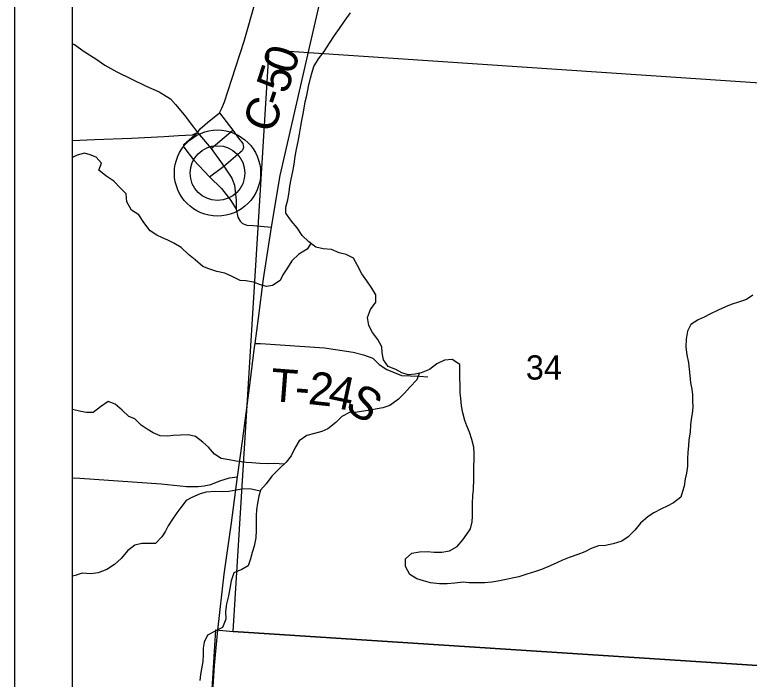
# Model space of a CAD drawing. Extents: x 0 to 34, y 0 to 22.
# Drawn here: x 23.417 to 24.685, y 19.088 to 20.236 of the extents above; entities that cross this region are included whole.
import ezdxf

# ---------------------------------------------------------------- set-up
doc = ezdxf.new("R2010")
doc.units = 0
for name, color, linetype in [('GM_X_County_Road', 7, 'Continuous'), ('GM_X_County_Road_Text', 7, 'Continuous'), ('GM_X_Minor_River', 7, 'Continuous'), ('GM_X_Section', 7, 'Continuous'), ('GM_X_Section_Text', 7, 'Continuous'), ('GM_X_State_Route', 7, 'Continuous'), ('GM_X_Township_Road', 7, 'Continuous'), ('GM_X_Township_Road_Text', 7, 'Continuous'), ('GM_X_Unincorporated', 7, 'Continuous'), ('GM_X_Unincorporated_Location', 7, 'Continuous'), ('SH_Data', 7, 'Continuous')]:
    doc.layers.add(name, color=color, linetype=linetype)

msp = doc.modelspace()

# ---------------------------------------------------------------- linework, layer by layer
at = {"layer": 'GM_X_County_Road'}
for points in [[(23.7323, 20.033), (23.737, 20.0391), (23.7498, 20.0501), (23.7703, 20.0665), (23.7745, 20.0748), (23.779, 20.0858), (23.7916, 20.1246), (23.8127, 20.1904), (23.833, 20.2612), (23.8405, 20.2846), (23.8637, 20.3631), (23.8706, 20.3822), (23.8749, 20.3912)], [(23.5167, 20.019), (23.5544, 20.0206), (23.6182, 20.0227), (23.675, 20.0261), (23.6994, 20.0275), (23.7237, 20.0287), (23.7323, 20.033), (23.7558, 20.005), (23.7778, 19.9748), (23.7918, 19.9541), (23.7964, 19.9419), (23.799, 19.9157), (23.799, 19.9003), (23.8022, 19.8863), (23.8061, 19.8796), (23.8102, 19.8755), (23.8176, 19.8729), (23.8286, 19.872), (23.8599, 19.8692)]]:
    msp.add_lwpolyline(points, dxfattribs=at)
at = {"layer": 'GM_X_Minor_River'}
for points in [[(24.1853, 19.6088), (24.1856, 19.6217), (24.1852, 19.632), (24.1719, 19.6407), (24.1591, 19.6395), (24.1455, 19.633), (24.133, 19.6235), (24.1186, 19.6178), (24.1081, 19.6151), (24.0959, 19.6143), (24.0853, 19.6177), (24.0751, 19.6234), (24.0618, 19.6286), (24.0535, 19.64), (24.0515, 19.6529), (24.0507, 19.6623), (24.0435, 19.6752), (24.0348, 19.6873), (24.0283, 19.6994), (24.026, 19.7131), (24.0312, 19.7271), (24.0403, 19.74), (24.0402, 19.7522), (24.0334, 19.7639), (24.025, 19.7764), (24.0159, 19.7889), (24.0086, 19.8029), (24.0018, 19.8158), (23.9889, 19.8222), (23.9768, 19.8252), (23.9635, 19.8308), (23.9491, 19.8316), (23.9366, 19.8346), (23.9245, 19.844), (23.9131, 19.855), (23.9043, 19.8682), (23.8948, 19.8799), (23.885, 19.8936), (23.8849, 19.9038), (23.8883, 19.9163), (23.8905, 19.9296), (23.892, 19.9402), (23.8942, 19.9523), (23.8968, 19.9656), (23.8991, 19.9778), (23.9009, 19.9914), (23.9031, 20.0039), (23.9061, 20.0172), (23.9087, 20.0297), (23.911, 20.0434), (23.9128, 20.0536), (23.9151, 20.065), (23.9165, 20.0748), (23.9184, 20.0858), (23.921, 20.0968), (23.924, 20.1124), (23.9274, 20.1264), (23.9304, 20.1367), (23.9333, 20.1465), (23.9413, 20.1602), (23.9511, 20.1727), (23.9605, 20.1868), (23.9691, 20.2001), (23.9778, 20.2122), (23.9861, 20.2251), (23.9963, 20.2392)], [(23.9282, 19.8411), (23.9215, 19.8311), (23.9075, 19.8224), (23.8954, 19.811), (23.8879, 19.7992), (23.88, 19.7867), (23.8751, 19.7772), (23.8619, 19.7684), (23.8513, 19.7669), (23.8414, 19.7695), (23.8293, 19.774), (23.8161, 19.7766), (23.8058, 19.777), (23.7922, 19.7842), (23.7793, 19.7898), (23.7657, 19.7924), (23.752, 19.7973), (23.7418, 19.8015), (23.7285, 19.8128), (23.7171, 19.8223), (23.7042, 19.834), (23.6913, 19.8419), (23.6814, 19.8468), (23.672, 19.851), (23.6621, 19.8555), (23.6504, 19.863), (23.6397, 19.8774), (23.6313, 19.8907), (23.6184, 19.8986), (23.6104, 19.913), (23.6093, 19.9266), (23.5994, 19.9368), (23.5876, 19.9489), (23.5743, 19.958), (23.5622, 19.9678), (23.5663, 19.9796), (23.5572, 19.9902), (23.547, 19.9943), (23.5375, 19.997), (23.5246, 19.9935), (23.5167, 19.9895)], [(24.6913, 19.7519), (24.6804, 19.7446), (24.6683, 19.7404), (24.6539, 19.7355), (24.6441, 19.7317), (24.6316, 19.7259), (24.6172, 19.7191)], [(24.6172, 19.7191), (24.6074, 19.7138), (24.5972, 19.7092), (24.584, 19.7012), (24.5783, 19.6894), (24.5761, 19.6761), (24.5754, 19.6621), (24.5773, 19.6489), (24.5804, 19.6352), (24.5812, 19.6238), (24.5824, 19.6132), (24.5839, 19.6003), (24.5859, 19.5897), (24.587, 19.5795), (24.5874, 19.5696), (24.5875, 19.5583), (24.5864, 19.5473), (24.5849, 19.5374), (24.5838, 19.5276), (24.5831, 19.515), (24.5808, 19.5021), (24.5805, 19.4923), (24.579, 19.4798), (24.5783, 19.4695), (24.5783, 19.4566), (24.5769, 19.4445), (24.5746, 19.4347), (24.5728, 19.4221), (24.5701, 19.4127), (24.5672, 19.4032), (24.5543, 19.3929), (24.5434, 19.3876), (24.5335, 19.383), (24.5203, 19.3758), (24.5105, 19.3697), (24.4976, 19.3579), (24.4875, 19.3461), (24.4761, 19.3343), (24.4652, 19.3267), (24.4501, 19.3221), (24.4372, 19.3194), (24.4247, 19.3187), (24.4119, 19.3141), (24.4013, 19.3087), (24.3892, 19.3038), (24.3741, 19.2988), (24.3627, 19.2939), (24.3529, 19.2897), (24.3415, 19.2843), (24.3264, 19.2782), (24.3158, 19.2744), (24.3011, 19.2698), (24.2871, 19.2656), (24.2757, 19.2633), (24.2655, 19.261), (24.2512, 19.2576), (24.2406, 19.2564), (24.2285, 19.2552), (24.2156, 19.2548), (24.2016, 19.2552), (24.1914, 19.2559), (24.177, 19.2544), (24.1634, 19.2532), (24.1505, 19.2532), (24.135, 19.255), (24.1228, 19.2584), (24.1111, 19.2618), (24.0993, 19.2693), (24.0913, 19.283), (24.0913, 19.2962), (24.1022, 19.3061), (24.1155, 19.3084), (24.1287, 19.3092), (24.1408, 19.3081), (24.1541, 19.3078), (24.1677, 19.3104), (24.1806, 19.3177), (24.1907, 19.3291), (24.1975, 19.339), (24.2039, 19.3484), (24.2069, 19.3602), (24.2073, 19.3701), (24.2072, 19.3921), (24.2079, 19.4061), (24.209, 19.4156), (24.2093, 19.4345), (24.2093, 19.4463), (24.2096, 19.4561), (24.2104, 19.4679), (24.2103, 19.4781), (24.2095, 19.4891), (24.2061, 19.5024), (24.2023, 19.5153), (24.1977, 19.5259), (24.1942, 19.5353), (24.1904, 19.5486), (24.1881, 19.5607), (24.1869, 19.5732), (24.1858, 19.5834), (24.1857, 19.5956), (24.1853, 19.6088)], [(24.1149, 19.6168), (24.1111, 19.6053), (24.099, 19.5931), (24.0896, 19.5825), (24.0794, 19.5722), (24.0647, 19.5615), (24.0526, 19.5573), (24.0428, 19.5554), (24.0303, 19.5531), (24.0197, 19.5512), (24.0083, 19.55), (23.9951, 19.5489), (23.9815, 19.542), (23.9713, 19.5317), (23.9577, 19.5207), (23.9471, 19.5161), (23.9343, 19.5131), (23.9214, 19.5093), (23.9082, 19.5005), (23.9006, 19.4876), (23.8943, 19.4743), (23.8856, 19.4633), (23.8739, 19.4527), (23.8607, 19.439), (23.8509, 19.4261), (23.8411, 19.415), (23.8381, 19.4048), (23.8358, 19.3927), (23.834, 19.3813), (23.8336, 19.3707), (23.8337, 19.3559), (23.8337, 19.3457), (23.833, 19.3328), (23.83, 19.3183), (23.827, 19.3073), (23.8237, 19.2967), (23.8199, 19.2842), (23.809, 19.2781), (23.7953, 19.2724), (23.7905, 19.2584), (23.7882, 19.2451), (23.786, 19.2326), (23.7826, 19.2189), (23.7808, 19.2056), (23.7812, 19.192), (23.7756, 19.1776), (23.7627, 19.1715), (23.7495, 19.1646), (23.7439, 19.1525), (23.7424, 19.1422), (23.7424, 19.1309), (23.7417, 19.1191), (23.7395, 19.1066), (23.7376, 19.0967), (23.7361, 19.0861)], [(23.8817, 19.4597), (23.8655, 19.461), (23.8538, 19.4606), (23.8398, 19.4609), (23.8262, 19.462), (23.8163, 19.4628), (23.7993, 19.4654), (23.7871, 19.4672), (23.7735, 19.4695), (23.7618, 19.477), (23.7511, 19.4891), (23.7416, 19.4982), (23.7287, 19.5077), (23.7162, 19.5107), (23.703, 19.5099), (23.6905, 19.5095), (23.6806, 19.5083), (23.6678, 19.5086), (23.656, 19.5143), (23.6454, 19.5203), (23.6352, 19.5271), (23.6241, 19.5381), (23.6135, 19.5422), (23.6021, 19.5532), (23.5904, 19.5638), (23.5782, 19.5679), (23.5646, 19.5592), (23.5522, 19.5493), (23.5405, 19.5489), (23.5306, 19.5508), (23.5167, 19.5544)], [(23.8406, 19.4135), (23.8225, 19.4173), (23.8093, 19.4169), (23.7994, 19.4153), (23.7866, 19.4126), (23.7756, 19.4119), (23.7627, 19.4126), (23.7476, 19.4118), (23.737, 19.4087), (23.7226, 19.4022), (23.7128, 19.3973), (23.7038, 19.3851), (23.6966, 19.3756), (23.6879, 19.3635), (23.6819, 19.3536), (23.677, 19.3441), (23.671, 19.3346), (23.6597, 19.3229), (23.6362, 19.3228), (23.6241, 19.3201), (23.6116, 19.3102), (23.6003, 19.2973), (23.589, 19.2867), (23.5758, 19.2783), (23.561, 19.2722), (23.5482, 19.2707), (23.5334, 19.2718), (23.5213, 19.2679), (23.5167, 19.2666)]]:
    msp.add_lwpolyline(points, dxfattribs=at)
at = {"layer": 'GM_X_Section'}
for points in [[(24.8672, 20.1076), (24.8107, 19.1055), (24.788, 19.1066), (23.7939, 19.171), (23.856, 20.1758)], [(23.7643, 19.174), (23.7939, 19.171), (24.788, 19.1066), (24.7175, 18.0761), (23.7006, 18.1492)]]:
    msp.add_lwpolyline(points, close=True, dxfattribs=at)
at = {"layer": 'GM_X_State_Route'}
for points in [[(23.8012, 19.4381), (23.8098, 19.4995), (23.8164, 19.5483), (23.8228, 19.5962), (23.8308, 19.6618), (23.8317, 19.6681), (23.8378, 19.712), (23.8466, 19.7798), (23.8599, 19.8692), (23.875, 19.9586), (23.9292, 20.1943), (23.96, 20.3273), (23.9665, 20.3566)], [(23.7042, 18.1483), (23.71, 18.2567), (23.7163, 18.3616), (23.7166, 18.3673), (23.7229, 18.4696), (23.7282, 18.5549), (23.7307, 18.6019), (23.7382, 18.7246), (23.7401, 18.752), (23.743, 18.7962), (23.7497, 18.9118), (23.7506, 18.9339), (23.7569, 19.0384), (23.7617, 19.1125), (23.7675, 19.1733), (23.7785, 19.2701), (23.7909, 19.3586), (23.8012, 19.4381)]]:
    msp.add_lwpolyline(points, dxfattribs=at)
at = {"layer": 'GM_X_Township_Road'}
msp.add_line((23.7558, 20.005), (23.7936, 20.0369), dxfattribs=at)
for points in [[(23.5167, 20.1861), (23.5199, 20.1845), (23.5366, 20.1727), (23.5569, 20.1597), (23.5725, 20.1491), (23.5932, 20.1374), (23.6436, 20.1128), (23.6661, 20.103), (23.6858, 20.0907), (23.6943, 20.0809), (23.7092, 20.063), (23.7256, 20.0417), (23.7323, 20.033)], [(23.7703, 20.0665), (23.7936, 20.0369), (23.8034, 20.0228), (23.8105, 20.0135), (23.8119, 20.007), (23.8101, 20.0023)], [(23.7085, 20.0076), (23.709, 20.0123), (23.7323, 20.033)], [(23.7085, 20.0076), (23.7256, 19.9853), (23.7533, 19.9559), (23.7737, 19.9359), (23.7898, 19.9152), (23.799, 19.9003)], [(23.7533, 19.9559), (23.7778, 19.9748), (23.8101, 20.0023)], [(23.8317, 19.6681), (23.8409, 19.6683), (23.9519, 19.6608), (24.0012, 19.6536), (24.0188, 19.6489), (24.0353, 19.6432), (24.0461, 19.6322), (24.0594, 19.6234), (24.0847, 19.6132), (24.1158, 19.6119), (24.1304, 19.611)], [(23.5167, 19.4365), (23.5289, 19.4357), (23.6696, 19.4259), (23.7133, 19.4215), (23.7333, 19.4213), (23.7438, 19.4225), (23.7554, 19.4251), (23.771, 19.4309), (23.7878, 19.4364), (23.8012, 19.4381)]]:
    msp.add_lwpolyline(points, dxfattribs=at)
at = {"layer": 'GM_X_Unincorporated'}
for radius in [0.0744, 0.0472]:
    msp.add_circle((23.7669, 19.9627), radius, dxfattribs=at)
at = {"layer": 'GM_X_Unincorporated_Location'}
msp.add_line((23.7669, 19.9627), (23.7669, 19.9627), dxfattribs=at)
at = {"layer": 'SH_Data'}
for points in [[(23.4167, 21), (30.4167, 21), (30.4167, 14), (23.4167, 14)], [(23.5167, 20.9), (30.3167, 20.9), (30.3167, 14.1), (23.5167, 14.1)]]:
    msp.add_lwpolyline(points, close=True, dxfattribs=at)

# ---------------------------------------------------------------- texts
at = {"layer": 'GM_X_County_Road_Text'}
for s, rotation, p in [('0', 72.146, (23.8977, 20.1312)), ('5', 72.0085, (23.8868, 20.0977)), ('-', 71.6598, (23.8793, 20.0752)), ('C', 69.0045, (23.8616, 20.0289))]:
    msp.add_text(s, height=0.0568, rotation=rotation, dxfattribs=at).set_placement(p)
at = {"layer": 'GM_X_Section_Text'}
msp.add_text('34', height=0.04186, rotation=0, dxfattribs=at).set_placement((24.2994, 19.606))
at = {"layer": 'GM_X_Township_Road_Text'}
for s, rotation, p in [('T', 355.6115, (23.8569, 19.5691)), ('2', 353.8736, (23.9221, 19.564)), ('4', 347.9736, (23.9554, 19.5605)), ('-', 355.3271, (23.8992, 19.5659)), ('S', 327.4618, (23.9846, 19.5553))]:
    msp.add_text(s, height=0.0568, rotation=rotation, dxfattribs=at).set_placement(p)

doc.saveas('drawing.dxf')
